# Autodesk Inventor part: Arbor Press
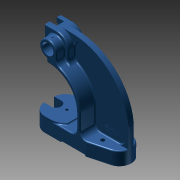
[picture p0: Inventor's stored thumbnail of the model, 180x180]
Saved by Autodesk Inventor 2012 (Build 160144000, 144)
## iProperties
Shininess: 64.0
Length Units: 11272
Angle Units: 11279
Time Units: 11290
Mass Units: 11286
Length Display Precision: 3
Angle Display Precision: 2
Compacted: True
Part Number: Arbor Press
Document SubType Name: Modeling
Created: 2003-11
Designer: Autodesk, Inc.
Manufacturer: Standard
Standards Organization: Custom
Mass: 6013.13 g
Surface Area: 1633.45 cm^2
Volume: 766.003 cm^3
Density: 7.85 g/cm^3
Material: Cast Steel
Density: 0.0
Volumn: 0.0
Area: 0.0
PropertySet Name: Model Information
Control State: 0
Master: False
Checked Out: False
Title: Arbor Press
Author: Autodesk, Inc.
Revision Number: A
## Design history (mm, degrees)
sketch "Sketch7"
  geometry: L1 (0, 0)-(0, 38.1); L2 (0, 38.1)-(79.375, 38.1); L3 (79.375, 38.1)-(79.375, 34.925); L4 (79.375, 34.925)-(117.475, 34.925); L5 (41.275, 165.1)-(11.201, 165.1); L6 (11.201, 165.1)-(11.201, 228.6); L7 (11.201, 228.6)-(66.675, 228.6); L8 (219.075, 76.2)-(219.075, 0); L9 (219.075, 0)-(141.275, 0); L10 (141.275, 0)-(0, 0); L11 (117.475, 34.925)-(117.475, 88.9); A1 r 152.4 centre (66.675, 76.2) between (219.075, 76.2) and (66.675, 228.6); A2 r 76.2 centre (41.275, 88.9) between (117.475, 88.9) and (41.275, 165.1)
  constraints: 22 end point, 8 parallel, 4 point on circle, 4 tangent, 2 centre point, 2 perpendicular, 1 collinear, 1 vertical
  dimensions: "d46" = 79.375 distance of L1.end L2.end; "d47" = 38.1 distance of L1.start L1.end; "d52" = 219.075 distance between parallel lines of L8 L1; "d53" = 228.6 distance between parallel lines of L10 L7; "d54" = 3.175 distance between parallel lines of L4 L2; "d55" = 152.4 radius of A1; "d56" = 76.2 radius of A2; "d57" = 63.5 distance of L5.end L6.end; "d59" = 25.4 horizontal distance of A1.centre A2.centre; "d60" = 30.0736 horizontal distance of A2.centre L5.end
extrude "Extrusion6" new body sketch "Sketch7" distance "d61" = 88.9; taper "d62" = 0 deg
sketch "Sketch8"
  geometry: L1 (207.874, 0)-(55.474, 0) reference; L2 (0, 0)-(55.474, 0) reference; L3 (-11.201, 0)-(68.174, 0) reference; L4 (-11.201, 0)-(-11.201, -88.9) reference; L5 (-11.201, -88.9)-(68.174, -88.9) reference; L6 (207.874, -88.9)-(55.474, -88.9) reference; L7 (207.874, 0)-(207.874, -88.9) reference; L8 (-11.201, -44.45)-(207.874, -44.45); L9 (-11.201, -44.45)-(-11.201, -33.325); L10 (22.123, 0)-(132.907, 0); L11 (132.907, 0)-(184.341, -13.782); L12 (22.123, -88.9)-(132.907, -88.9); L13 (132.907, -88.9)-(184.341, -75.118); L14 (-11.201, -44.45)-(-11.201, -55.575); A1 r 33.325 centre (22.123, -33.325) between (22.123, 0) and (-11.201, -33.325); A2 r 31.75 centre (176.124, -44.45) between (207.874, -44.45) and (184.341, -13.782); A3 r 33.325 centre (22.123, -55.575) between (-11.201, -55.575) and (22.123, -88.9); A4 r 31.75 centre (176.124, -44.45) between (184.341, -75.118) and (207.874, -44.45)
  constraints: 14 end point, 8 point on circle, 5 symmetric about line, 4 centre point, 4 point on line, 4 tangent, 2 midpoint, 1 collinear, 4 other
  dimensions: "d63" = 15 deg angle of L1 L11; "d64" = 33.3248 radius of A1; "d65" = 31.75 radius of A2
extrude "Extrusion7" sketch "Sketch8" stored distance "d66" = 88.9; taper "d67" = 0 deg
sketch "Sketch9"
  geometry: L1 (141.275, 3.175)-(76.2, 3.175) reference; L2 (144.108, 0)-(195.543, 0) reference; L3 (79.375, 34.925)-(117.475, 34.925) reference; L4 (117.475, 34.925)-(117.475, 88.9) reference; L5 (219.075, 34.925)-(127, 34.925); L6 (219.075, 76.2)-(219.075, 0) reference; L7 (11.201, 228.6)-(11.201, 165.1) reference; L8 (219.075, 34.925)-(219.075, 76.2); L9 (127, 88.9)-(127, 34.925); L10 (73.025, 228.6)-(73.025, 168.529); L11 (33.325, 228.6)-(66.675, 228.6) reference; A1 r 76.2 centre (41.275, 88.9) between (117.475, 88.9) and (41.275, 165.1) reference; A2 r 152.4 centre (66.675, 76.2) between (144.108, 207.463) and (66.675, 228.6) reference; A3 r 152.4 centre (66.675, 76.2) between (195.543, 157.557) and (144.108, 207.463) reference; A4 r 152.401 centre (66.674, 76.2) between (219.075, 76.2) and (195.543, 157.557); A5 r 152.4 centre (66.675, 76.2) between (195.543, 157.557) and (144.108, 207.463); A6 r 85.725 centre (41.275, 88.9) between (127, 88.9) and (73.025, 168.529); A7 r 152.4 centre (66.675, 76.2) between (144.108, 207.463) and (73.025, 228.468)
  constraints: 8 end point, 8 point on circle, 4 centre point, 3 concentric, 2 point on line, 1 collinear
  dimensions: "d86" = 9.525 distance between parallel lines of L9 L4; "d87" = 61.8236 distance between parallel lines of L10 L7; "d88" = 85.725 radius of A6; "d89" = 152.40105 radius of A4
workplane "Work Plane2"
extrude "Extrusion9" cut sketch "Sketch9" distance "d90" = 37.3126; taper "d91" = 0 deg
sketch "Sketch12"
  geometry: L1 (127, 34.925)-(127, 88.9) reference; L2 (144.108, 34.925)-(127, 34.925) reference; L3 (195.543, 34.925)-(144.108, 34.925) reference; L4 (195.543, 34.925)-(218.262, 34.925) reference; L5 (127, 88.9)-(127, 34.925); L6 (218.262, 91.917)-(218.262, 34.925) reference; L7 (208.737, 91.417)-(208.737, 34.925); L8 (66.212, 219.075)-(66.675, 219.075); L9 (208.737, 34.925)-(127, 34.925); L10 (73.025, 168.529)-(73.025, 218.934); L11 (73.025, 228.468)-(73.025, 228.6); A1 r 85.725 centre (41.275, 88.9) between (127, 88.9) and (73.025, 168.529) reference; A2 r 85.725 centre (41.275, 88.9) between (127, 88.9) and (73.025, 168.529); A3 r 152.4 centre (66.675, 76.2) between (195.543, 157.557) and (66.675, 228.6) reference; A4 r 152.401 centre (66.674, 76.2) between (218.262, 91.917) and (195.543, 157.557) reference; A5 r 142.875 centre (66.675, 76.2) between (187.488, 152.472) and (73.025, 218.934); A6 r 142.876 centre (66.674, 76.2) between (208.737, 91.417) and (187.488, 152.472); A7 r 85.725 centre (41.275, 88.9) between (127, 88.9) and (73.025, 168.529) reference; 2 further points; 1 other entity
  constraints: 12 end point, 9 point on circle, 3 centre point, 2 tangent, 1 collinear, 1 concentric, 1 point on line, 1 other
  dimensions: "d93" = 9.525 radial gap between concentric circles of A3 A5; "d94" = 9.525 distance between parallel lines of L6 L7; "d99" = 0 horizontal extent of L10; "d100" = 9.525 radial gap between concentric circles of A4 A6
extrude "Extrusion10" cut sketch "Sketch12" distance "d96" = 3.175; taper "d97" = 0 deg
sketch "Sketch13"
  geometry: L1 (33.325, 165.1)-(11.201, 165.1) reference; L2 (11.201, 228.6)-(11.201, 165.1) reference; L3 (11.201, 228.6)-(33.325, 228.6) reference; L4 (33.325, 228.6)-(66.675, 228.6) reference; L5 (41.275, 165.1)-(33.325, 165.1) reference; L6 (38.1, 165.1)-(38.1, 174.853); L7 (11.201, 196.85)-(77.125, 196.85); L8 (63.5, 196.85)-(63.5, 171.694); L9 (73.025, 168.529)-(73.025, 228.468) reference; L10 (38.1, 165.1)-(11.201, 165.1); L11 (11.201, 165.1)-(11.201, 228.6); L12 (73.025, 228.468)-(73.025, 168.529); L13 (12.066, 228.6)-(66.675, 228.6); A1 r 76.2 centre (41.275, 88.9) between (117.475, 88.9) and (41.275, 165.1) reference; A2 r 152.4 centre (66.675, 76.2) between (73.025, 228.468) and (66.675, 228.6) reference; A3 r 22.225 centre (41.275, 196.85) between (63.5, 196.85) and (38.1, 174.853); A4 r 85.725 centre (41.275, 88.9) between (127, 88.9) and (73.025, 168.529) reference; A5 r 85.725 centre (41.275, 88.9) between (73.025, 168.529) and (63.5, 171.694); A6 r 152.4 centre (66.675, 76.2) between (73.025, 228.468) and (66.675, 228.6)
  constraints: 14 end point, 6 point on circle, 4 perpendicular, 4 point on line, 3 centre point, 3 collinear, 2 concentric, 2 tangent, 1 midpoint
  dimensions: "d101" = 44.45 diameter of A3; "d102" = 30.0736 distance from line of L2 A3.centre; "d103" = 3.175 distance from line of A3.centre L6; "d105" = 9.525 radial gap between concentric circles of A1 A5
extrude "Extrusion11" cut sketch "Sketch13" distance "d106" = 22.225; taper "d107" = 0 deg
mirror "Mirror3"
sketch "Sketch14"
  geometry: L1 (0, 63.5)-(58.272, 63.5) reference; L2 (-8.403, 63.5)-(0, 63.5) reference; L3 (-8.403, 63.5)-(-8.403, 0) reference; L4 (0, 0)-(58.272, 0) reference; L5 (58.272, 0)-(58.272, 63.5) reference; L6 (58.272, 53.975)-(80.497, 53.975) reference; L7 (80.497, 52.504)-(80.497, 10.996) reference; L8 (80.497, 31.75)-(80.497, 53.975) reference; L9 (80.497, 9.753)-(80.497, 0) reference; L10 (80.497, 9.753)-(80.497, 10.996) reference; L11 (80.497, 0)-(58.272, 0) reference; L12 (13.822, 63.5)-(13.822, 9.525); L13 (13.822, 63.5)-(-8.403, 63.5); L14 (-8.403, 63.5)-(-8.403, 9.525); L15 (-8.403, 9.525)-(13.822, 9.525); L16 (0, 0)-(-8.403, 0) reference
  constraints: 8 end point, 3 perpendicular, 1 point on line
  dimensions: "d109" = 44.45 distance between parallel lines of L5 L12; "d111" = 9.525 distance between parallel lines of L4 L15
extrude "Extrusion12" cut sketch "Sketch14" stored distance "d112" = 22.225; taper "d113" = 0 deg
sketch "Sketch16"
  geometry: L1 (-33.325, 174.625)-(-73.025, 174.625) reference; L2 (-33.325, 174.625)-(-33.325, 165.1) reference; L3 (-73.025, 174.625)-(-73.025, 168.529) reference; L4 (-73.025, 168.529)-(-73.025, 174.625); L5 (-73.025, 174.625)-(-41.275, 174.625); A1 r 85.725 centre (-41.275, 88.9) between (-73.025, 168.529) and (-127, 88.9) reference; A2 r 85.725 centre (-41.275, 88.9) between (-41.275, 174.625) and (-73.025, 168.529)
  constraints: 4 end point, 2 collinear, 2 point on circle, 2 tangent, 1 centre point, 1 concentric, 1 point on line
extrude "Extrusion13" cut sketch "Sketch16" distance "d116" = 22.225; taper "d117" = 0 deg
workplane "Work Plane5"
sketch "Sketch17"
  geometry: L1 (11.201, 228.6)-(11.201, 174.625) reference; L2 (66.675, 228.6)-(11.201, 228.6) reference; L3 (73.025, 168.529)-(73.025, 228.468) reference; L4 (11.201, 215.9)-(41.275, 215.9); L5 (41.275, 177.8)-(11.201, 177.8); L6 (33.325, 165.1)-(11.201, 165.1) reference; A1 r 152.4 centre (66.675, 76.2) between (73.025, 228.468) and (66.675, 228.6) reference; A2 r 19.05 centre (41.275, 196.85) between (41.275, 177.8) and (41.275, 215.9)
  constraints: 4 end point, 2 point on circle, 2 point on line, 1 centre point, 1 parallel, 1 tangent
  dimensions: "d120" = 38.1 distance between parallel lines of L5 L4; "d121" = 19.05 radius of A2; "d122" = 12.7 distance of L1.start L4.start; "d123" = 12.7 distance of L6.end L5.end; "d124" = 30.0736 distance from line of L1 A2.centre
extrude "Extrusion14" cut sketch "Sketch17" stored distance "d125" = 25.4; taper "d126" = 0 deg
sketch "Sketch18"
  geometry: C1 r 14.879 at (41.275, 196.85); A1 r 22.225 centre (41.275, 196.85) between (63.5, 196.85) and (33.325, 217.604) reference
  constraints: 1 centre point, 1 coincident
  dimensions: "d127" = 29.758 diameter of C1
extrude "Extrusion15" cut sketch "Sketch18" distance "d128" = 38.1; taper "d129" = 0 deg
sketch "Sketch19"
  geometry: C1 r 9.538 at (41.275, 196.85); A1 r 22.225 centre (41.275, 196.85) between (63.5, 196.85) and (33.325, 217.604) reference; 2 further points
  constraints: 1 centre point, 1 coincident
  dimensions: "d130" = 19.0754 diameter of C1
extrude "Extrusion16" cut sketch "Sketch19" distance "d131" = 25.4; taper "d132" = 0 deg
fillet "Fillet2" dims "d134" = 15.875
fillet "Fillet3" dims "d135" = 15.875
sketch "Sketch20"
  geometry: L1 (11.201, 228.6)-(66.675, 228.6) reference; L2 (73.025, 228.468)-(73.025, 178.646) reference; L3 (41.275, 228.6)-(66.675, 228.6); L4 (73.025, 228.468)-(73.025, 196.85); C1 r 9.538 at (41.275, 196.85) reference; A1 r 31.75 centre (41.275, 196.85) between (73.025, 196.85) and (41.275, 228.6); A2 r 152.4 centre (66.675, 76.2) between (73.025, 228.468) and (66.675, 228.6) reference; A3 r 152.4 centre (66.675, 76.2) between (73.025, 228.468) and (66.675, 228.6)
  constraints: 4 end point, 4 point on circle, 2 centre point, 2 point on line, 2 tangent, 1 coincident, 1 collinear, 1 concentric
extrude "Extrusion17" cut sketch "Sketch20" distance "d136" = 15.0876; taper "d137" = 0 deg
mirror "Mirror4"
fillet "Fillet4" dims "d138" = 15.875
fillet "Fillet5" dims "d139" = 3.175
fillet "Fillet6" dims "d140" = 3.175
fillet "Fillet7" dims "d141" = 15.875
sketch "Sketch22"
  geometry: L1 (-79.375, 55.575)-(-79.375, 33.325) reference; L2 (-46.05, 0)-(0, 0) reference; L3 (-46.05, 88.9)-(0, 88.9) reference; L4 (-79.375, 44.45)-(-18.816, 44.45); L5 (-60.325, 57.944)-(-79.375, 57.944); L6 (-79.375, 30.956)-(-60.325, 30.956); L7 (-79.375, 57.944)-(-79.375, 30.956); A1 r 33.325 centre (-46.05, 55.575) between (-46.05, 88.9) and (-79.375, 55.575) reference; A2 r 33.325 centre (-46.05, 33.325) between (-79.375, 33.325) and (-46.05, 0) reference; A3 r 13.494 centre (-60.325, 44.45) between (-60.325, 30.956) and (-60.325, 57.944)
  constraints: 8 end point, 3 perpendicular, 3 point on line, 2 point on circle, 2 tangent, 1 centre point, 1 midpoint, 1 parallel
  dimensions: "d147" = 26.9875 diameter of A3; "d148" = 19.05 distance of L4.start A3.centre
extrude "Extrusion19" cut sketch "Sketch22" stored distance "d149" = 3.175; taper "d150" = 0 deg
sketch "Sketch23"
  geometry: L1 (0, 88.9)-(0, 0) reference; L2 (-46.05, 0)-(0, 0) reference; L3 (-60.325, 44.45)-(-10.181, 44.45); L4 (0, 13.341)-(0, 0); L5 (0, 0)-(-31.75, 0); A1 r 44.45 centre (-31.75, 44.45) between (-31.75, 0) and (0, 13.341); A2 r 13.494 centre (-60.325, 44.45) between (-60.325, 30.956) and (-60.325, 57.944) reference
  constraints: 6 end point, 3 point on line, 2 point on circle, 1 centre point, 1 parallel, 1 perpendicular
  dimensions: "d151" = 88.9 diameter of A1; "d153" = 28.575 distance of A1.centre L3.start
extrude "Extrusion20" cut sketch "Sketch23" distance "d154" = 3.175; taper "d155" = 0 deg
mirror "Mirror5"
fillet "Fillet10" dims "d157" = 15.875
fillet "Fillet11" dims "d158" = 15.875
fillet "Fillet12" dims "d159" = 15.875
fillet "Fillet15" dims "d162" = 15.875
sketch "Sketch24"
  geometry: L1 (-33.241, 57.944)-(-14.275, 57.944) reference; L2 (-14.275, 30.956)-(-33.241, 30.956) reference; L3 (110.783, 0)-(0, 0) reference; L4 (162.218, 13.782)-(110.783, 0) reference; L5 (110.783, 88.9)-(162.218, 75.118) reference; L6 (110.783, 88.9)-(0, 88.9) reference; L7 (0, 80.975)-(109.74, 80.975); L8 (109.74, 80.975)-(160.167, 67.463); L9 (160.167, 21.437)-(109.74, 7.925); L10 (109.74, 7.925)-(0, 7.925); L11 (-23.221, 23.031)-(-14.275, 23.031); L12 (-14.275, 65.869)-(-23.221, 65.869); A1 r 13.494 centre (-14.275, 44.45) between (-14.275, 30.956) and (-14.275, 57.944) reference; A2 r 33.325 centre (0, 33.325) between (-33.241, 30.956) and (0, 0) reference; A3 r 31.75 centre (154, 44.45) between (162.218, 13.782) and (162.218, 75.118) reference; A4 r 33.325 centre (0, 55.575) between (0, 88.9) and (-33.241, 57.944) reference; A5 r 23.825 centre (154, 44.45) between (160.167, 21.437) and (160.167, 67.463); A6 r 25.4 centre (0, 33.325) between (-23.221, 23.031) and (0, 7.925); A7 r 21.419 centre (-14.275, 44.45) between (-14.275, 23.031) and (-14.275, 65.869); A8 r 25.4 centre (0, 55.575) between (0, 80.975) and (-23.221, 65.869)
  constraints: 12 end point, 8 point on circle, 4 centre point, 9 other
  dimensions: "d163" = 7.9248 distance between parallel lines of L7 L6
extrude "Extrusion21" cut sketch "Sketch24" distance "d164" = 26.9875; taper "d165" = 0 deg
sketch "Sketch25"
  geometry: L1 (144.108, 0)-(33.325, 0) reference; L2 (33.325, 0)-(0.084, 0) reference; L3 (0.084, 38.1)-(0.084, 0) reference; L4 (76.284, 0)-(76.284, 3.175); L5 (76.284, 3.175)-(141.359, 3.175); L6 (141.359, 3.175)-(141.359, 0)
  constraints: 6 end point, 2 parallel, 2 point on line, 1 perpendicular
  dimensions: "d166" = 76.2 distance between parallel lines of L3 L4; "d167" = 65.0748 distance of L4.end L5.end; "d168" = 3.175 distance between parallel lines of L1 L5
extrude "Extrusion22" cut sketch "Sketch25" stored distance "d169" = 26.9875; taper "d170" = 0 deg
sketch "Sketch27"
  geometry: L1 (-23.221, 65.869)-(-14.275, 65.869) reference; L2 (-14.275, 23.031)-(-23.221, 23.031) reference; L3 (0, 7.925)-(109.74, 7.925) reference; L4 (109.74, 7.925)-(160.167, 21.437) reference; L5 (160.167, 67.463)-(109.74, 80.975) reference; L6 (109.74, 80.975)-(0, 80.975) reference; L7 (27, 80.975)-(27, 7.925); L8 (103.226, 80.975)-(103.226, 7.925); L9 (27, 80.975)-(103.226, 80.975); L10 (27, 7.925)-(103.226, 7.925); A1 r 25.4 centre (0, 55.575) between (0, 80.975) and (-23.221, 65.869) reference; A2 r 21.419 centre (-14.275, 44.45) between (-14.275, 23.031) and (-14.275, 65.869) reference; A3 r 25.4 centre (0, 33.325) between (-23.221, 23.031) and (0, 7.925) reference; A4 r 23.825 centre (154, 44.45) between (160.167, 21.437) and (160.167, 67.463) reference; A5 r 31.75 centre (154, 44.45) between (162.218, 13.782) and (162.218, 75.118) reference; 1 further point
  constraints: 8 end point, 4 point on line, 2 collinear, 2 perpendicular
  dimensions: "d176" = 60.325 distance from line of L7 point (-33.325, 0); "d178" = 50.7746 distance from line of A4.centre L8
extrude "Extrusion23" join sketch "Sketch27" distance "d179" = 12.6873; taper "d180" = 0 deg
workplane "Work Plane7"
sketch "Sketch28"
  geometry: L1 (-136.55, 14.3)-(-136.55, 26.988) reference; L2 (-60.325, 14.3)-(-136.55, 14.3) reference; L3 (-136.55, 26.988)-(-114.575, 14.3); L4 (-114.575, 14.3)-(-136.55, 14.3); L5 (-136.55, 14.3)-(-136.55, 26.988)
  constraints: 6 end point, 1 collinear, 1 perpendicular, 1 point on line
  dimensions: "d182" = 30 deg angle of L2 L3
extrude "Extrusion24" cut sketch "Sketch28" stored distance "d183" = 73.0504; taper "d184" = 0 deg
fillet "Fillet17" dims "d185" = 3.175
sketch "Sketch29"
  geometry: L1 (-58.272, 0)-(0, 0) reference; L2 (0, 0)-(0, 63.5) reference; L3 (-44.45, 63.5)-(0, 63.5) reference; L4 (-44.45, 63.5)-(-44.45, 9.525) reference; L5 (-58.272, 0)-(-58.272, 9.525) reference; L6 (-9.525, 50.8)-(-9.525, 12.7) reference; L7 (-9.525, 12.7)-(-34.925, 12.7) reference; L8 (-34.925, 12.7)-(-34.925, 50.8) reference; L9 (-34.925, 50.8)-(-9.525, 50.8) reference; L10 (-22.225, 63.5)-(-22.225, 0); L11 (-6.35, 57.15)-(-61.925, 57.15); L12 (-34.925, 31.75)-(-9.525, 31.75); L13 (-44.45, 9.525)-(-58.272, 9.525) reference; 3 further points
  constraints: 6 end point, 3 midpoint, 2 perpendicular, 2 point on line, 2 symmetric about line
  dimensions: "d186" = 31.75 distance of L11.start point (-38.1, 57.15); "d187" = 15.875 distance from line of L11.start L10; "d188" = 6.35 distance from line of L3 L11.start
hole "Hole1" sketch "Sketch29" at (-38.1, 57.15), (-6.35, 57.15), (-38.1, 6.35), (-6.35, 6.35) diameter "d189" = 4.9784; stored, may be unused: countersink angle "d193" = 82 deg, drill point angle "d195" = 118 deg; dims "d190" = 12.7, "d191" = 9.525, "d192" = 6.35, "d194" = 19.1008
sketch "Sketch30"
  geometry: L1 (-31.75, -49.954)-(-31.75, -31.75) reference; L2 (30.074, -53.975)-(0, -53.975) reference; L3 (30.074, 0)-(30.074, -53.975) reference; L4 (0, 0)-(30.074, 0) reference; L5 (20.549, -19.05)-(20.549, -44.45); L6 (30.074, -63.5)-(7.95, -63.5) reference; C1 r 9.538 at (0, -31.75) reference; A1 r 31.75 centre (0, -31.75) between (0, 0) and (-31.75, -31.75) reference; A2 r 15.875 centre (-47.625, -49.954) between (-40.184, -63.976) and (-31.75, -49.954) reference; A3 r 85.725 centre (0, -139.7) between (0, -53.975) and (-40.184, -63.976) reference; 1 further point
  constraints: 2 end point
  dimensions: "d196" = 25.4 distance of L5.start L5.end; "d197" = 9.525 distance from line of L3 L5.start; "d255" = 6.35 vertical distance of point (30.074, -50.8) L5.end; "d256" = 20.5486 horizontal distance of A1.centre L5.end
hole "Hole2" sketch "Sketch30" at (20.549, -19.05), (20.549, -44.45) diameter "d199" = 3.9624; stored, may be unused: countersink angle "d203" = 82 deg, drill point angle "d205" = 118 deg; dims "d200" = 12.7, "d201" = 9.525, "d202" = 6.35, "d204" = 19.05
sketch "Sketch31"
  geometry: C1 r 9.538 at (0, -31.75) reference; C2 r 17.45 at (0, -31.75)
  constraints: 1 centre point, 1 coincident
  dimensions: "d206" = 17.4498 radius of C2
extrude "Extrusion25" join sketch "Sketch31" distance "d207" = 9.525; taper "d208" = 0 deg
fillet "Fillet19" dims "d210" = 3.175
sketch "Sketch32"
  geometry: L1 (-42.85, 29.362)-(-42.85, 38.887) reference; L2 (-25.4, 38.887)-(-25.4, 5.475); L3 (-42.85, 38.887)-(-7.95, 38.887) reference; 1 further point
  constraints: 2 end point, 1 parallel, 1 point on line
  dimensions: "d290" = 4.7625 distance from line of L3 point (-25.4, 34.125)
hole "Hole3" sketch "Sketch32" at (-25.4, 34.125) diameter "d212" = 3.175; stored, may be unused: countersink angle "d216" = 82 deg, drill point angle "d218" = 118 deg; dims "d213" = 12.7, "d214" = 9.525, "d215" = 6.35, "d217" = 25.4
sketch "Sketch34"
  geometry: A1 r 13.494 centre (-173.812, 7.137) between (-173.812, -6.356) and (-173.812, 20.631) reference; 1 further point
  dimensions: "d228" = 142.875 horizontal distance of point (-30.937, -11.913) A1.centre; "d229" = 19.05 vertical distance of point (-30.937, -11.913) A1.centre
hole "Hole5" sketch "Sketch34" at (-30.937, -11.913) diameter "d230" = 10.3124; stored, may be unused: countersink angle "d234" = 82 deg, drill point angle "d236" = 118 deg; dims "d231" = 12.7, "d232" = 9.525, "d233" = 6.35, "d235" = 12.7
mirror "Mirror6"
sketch "Sketch35"
  geometry: A1 r 13.494 centre (18.966, -13.494) between (18.966, -26.988) and (18.966, 0) reference; 1 further point
  dimensions: "d237" = 28.575 distance of point (47.541, -13.494) A1.centre; "d238" = 0 vertical distance of A1.centre point (47.541, -13.494)
hole "Hole6" sketch "Sketch35" at (47.541, -13.494) diameter "d239" = 6.731; stored, may be unused: countersink angle "d243" = 82 deg, drill point angle "d245" = 118 deg; dims "d240" = 12.7, "d241" = 9.525, "d242" = 6.35, "d244" = 12.7
sketch "Sketch36"
  geometry: L1 (-58.272, 0)-(0, 0) reference; L2 (0, 0)-(0, 63.5) reference; L3 (-44.45, 63.5)-(0, 63.5) reference; L4 (-44.45, 63.5)-(-44.45, 9.525) reference; L5 (-58.272, 0)-(-58.272, 9.525) reference; L6 (-9.525, 50.8)-(-9.525, 12.7) reference; L7 (-9.525, 12.7)-(-34.925, 12.7) reference; L8 (-34.925, 12.7)-(-34.925, 50.8) reference; L9 (-34.925, 50.8)-(-9.525, 50.8) reference; L10 (-31.75, 63.5)-(-31.75, 50.8); L11 (-12.725, 63.5)-(-12.725, 50.8); L12 (-34.925, 31.75)-(-9.525, 31.75); L13 (-22.225, 50.8)-(-22.225, 31.75); L14 (-31.75, 63.5)-(-12.725, 63.5); L15 (-31.75, 50.8)-(-12.725, 50.8); L16 (-44.45, 9.525)-(-58.272, 9.525) reference; C1 r 2.489 at (-38.1, 6.35) reference; C2 r 2.489 at (-38.1, 57.15) reference; C3 r 2.489 at (-6.35, 57.15) reference; C4 r 2.489 at (-6.35, 6.35) reference
  constraints: 12 end point, 4 midpoint, 4 point on line, 3 perpendicular, 1 parallel
  dimensions: "d246" = 19.0246 distance between parallel lines of L11 L10; "d247" = 9.4996 distance between parallel lines of L11 L13
extrude "Extrusion26" cut sketch "Sketch36" distance "d248" = 19.1008; taper "d249" = 0 deg
workplane "Work Plane8"
mirror "Mirror7"
sketch "Sketch37"
  geometry: L1 (-11.201, 174.625)-(-41.275, 174.625) reference; L2 (-30.302, 165.1)-(-11.201, 165.1) reference; L3 (-11.201, 165.1)-(-11.201, 177.8) reference; L4 (-11.201, 174.625)-(-11.201, 165.1); L5 (-41.275, 174.625)-(-11.201, 174.625); L6 (-41.275, 174.625)-(-41.275, 165.1); L7 (-11.201, 165.1)-(-41.275, 165.1)
  constraints: 8 end point, 2 collinear, 2 perpendicular
extrude "Extrusion27" join sketch "Sketch37" distance "d251" = 12.7; taper "d252" = 0 deg
delete_face "Delete Face1"
sketch "Sketch39"
  geometry: L1 (180.803, 172.743)-(244.935, 172.743); L2 (244.935, 172.743)-(244.935, 72.014); L3 (244.935, 72.014)-(180.803, 72.014); L4 (180.803, 72.014)-(180.803, 172.743)
  constraints: 8 end point, 2 parallel, 1 horizontal, 1 perpendicular
extrude "Extrusion28" cut sketch "Sketch39" distance "d264" = 25.4; taper "d265" = 0 deg
mirror "Mirror8"
fillet "Fillet21" dims "d266" = 3.175
fillet "Fillet22" dims "d267" = 3.175
fillet "Fillet23" dims "d268" = 3.175
sketch "Sketch40"
  geometry: L1 (-3.175, -34.138)-(-30.956, -34.138) reference; L2 (-3.175, -34.138)-(-3.175, -18.263) reference; L3 (-30.956, -18.263)-(-3.175, -18.263) reference; L4 (-30.956, -34.138)-(-30.956, -18.263) reference; L5 (-47.625, -18.263)-(-47.625, -34.138) reference; L6 (-23.812, 34.125)-(-23.812, -34.138); L7 (-6.35, -37.313)-(-44.45, -37.313) reference; C1 r 1.587 at (-23.812, -26.213); 2 further points
  constraints: 2 end point, 2 point on line, 1 centre point, 1 perpendicular
  dimensions: "d272" = 3.175 diameter of C1; "d275" = 11.0998 distance from line of L7 C1.centre
extrude "Extrusion29" cut sketch "Sketch40" distance "d276" = 25.4; taper "d277" = 0 deg
sketch "Sketch41"
  geometry: L1 (22.225, 60.325)-(22.225, 9.525) reference; L2 (22.225, 9.525)-(0, 9.525) reference; L3 (0, 0)-(0, 9.525) reference; L4 (0, 0)-(34.925, 0) reference; L5 (34.925, 0)-(34.925, 12.7) reference; L6 (31.75, 12.7)-(31.75, 50.8) reference; L7 (34.925, 50.8)-(34.925, 63.5) reference; L8 (25.4, 63.5)-(34.925, 63.5) reference; L9 (22.225, 9.525)-(22.225, 0); L10 (22.225, 0)-(0, 0); L11 (0, 0)-(0, 9.525); L12 (0, 9.525)-(22.225, 9.525); L13 (34.925, 12.7)-(31.75, 12.7) reference; L14 (31.75, 50.8)-(34.925, 50.8) reference; C1 r 2.489 at (28.575, 57.15) reference; C2 r 2.489 at (28.575, 6.35) reference; A1 r 3.175 centre (25.4, 60.325) between (25.4, 63.5) and (22.225, 60.325) reference
  constraints: 8 end point, 2 collinear, 2 perpendicular, 1 point on line
extrude "Extrusion30" cut sketch "Sketch41" distance "d278" = 26.8986; taper "d279" = 0 deg
fillet "Fillet27" dims "d280" = 3.175
fillet "Fillet28" dims "d281" = 3.175
fillet "Fillet30" dims "d283" = 3.175
sketch "Sketch42"
  geometry: L1 (3.175, -31.75)-(3.175, -22.225) reference; L2 (-102.833, -196.85)-(-102.833, -165.1) reference; L3 (-102.833, -196.85)-(-100.084, -196.85) reference; L4 (-100.084, -193.675)-(-35.009, -193.675) reference; L5 (7.95, -158.75)-(7.95, -196.85) reference; L6 (7.95, -158.75)-(-6.35, -158.75) reference; L7 (3.175, -22.225)-(3.175, -17.159); L8 (-17.45, 0)-(-17.45, -24.02); L9 (0, -22.225)-(3.175, -22.225); L10 (-102.833, -165.1)-(-101.6, -165.1) reference; L11 (-82.55, -146.05)-(-82.55, -107.95) reference; L12 (-60.325, -165.1)-(-6.35, -165.1) reference; L13 (-79.375, -107.95)-(-79.375, -146.05) reference; L14 (3.175, -28.575)-(0, -28.575) reference; L15 (3.175, -28.575)-(3.175, -25.4) reference; L16 (0, -25.4)-(3.175, -25.4) reference; L17 (-100.084, -196.85)-(-100.084, -193.675) reference; L18 (-35.009, -193.675)-(-35.009, -196.85) reference; L19 (-35.009, -196.85)-(7.95, -196.85) reference; L20 (-6.35, -158.75)-(-6.35, -165.1) reference; A1 r 17.45 centre (0, 0) between (3.175, -17.159) and (-17.45, 0) reference; A2 r 17.45 centre (0, 0) between (-17.45, 0) and (3.175, -17.159); A3 r 85.725 centre (0, -107.95) between (0, -22.225) and (-17.45, -24.02); A4 r 82.55 centre (0, -107.95) between (0, -25.4) and (-82.55, -107.95) reference; A5 r 19.05 centre (-101.6, -146.05) between (-101.6, -165.1) and (-82.55, -146.05) reference; A6 r 19.05 centre (-60.325, -146.05) between (-79.375, -146.05) and (-60.325, -165.1) reference; A7 r 79.375 centre (0, -107.95) between (0, -28.575) and (-79.375, -107.95) reference
  constraints: 6 end point, 6 point on circle, 3 tangent, 2 centre point, 1 concentric, 1 parallel, 1 perpendicular
extrude "Extrusion31" join sketch "Sketch42" distance "d284" = 9.525; taper "d285" = 0 deg
fillet "Fillet31" dims "d286" = 3.175
fillet "Fillet32" dims "d287" = 3.175
fillet "Fillet33" dims "d288" = 3.175
fillet "Fillet34" dims "d289" = 3.175
sketch "Sketch43"
  geometry: L1 (123.521, 60.955)-(212.511, 60.955); L2 (212.511, 60.955)-(212.511, 48.209); L3 (212.511, 48.209)-(123.521, 48.209); L4 (123.521, 48.209)-(123.521, 60.955)
  constraints: 2 other
emboss "Emboss1" sketch "Sketch43" dims "d293" = 2.54, "d294" = 0
fillet "Fillet35" dims "d295" = 3.175
fillet "Fillet36" dims "d296" = 3.175
fillet "Fillet37" dims "d297" = 3.175
fillet "Fillet38" dims "d298" = 3.175
fillet "Fillet39" dims "d299" = 3.175
body "Solid1"
node "Projected Loop4"
node "Projected Loop5"
node "Projected Loop6"
node "Projected Loop7"
node "Projected Loop8"
node "Projected Loop9"
node "Projected Loop10"
node "Projected Loop11"
other parameters: "d32" = 47.625, "d33" = 47.625, "d39" = 47.625, "d76" = 61.8236, "d80" = -44.45, "d98" = 31.75, "d118" = -22.225, "d181" = -44.45, "d250" = -31.75
